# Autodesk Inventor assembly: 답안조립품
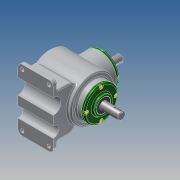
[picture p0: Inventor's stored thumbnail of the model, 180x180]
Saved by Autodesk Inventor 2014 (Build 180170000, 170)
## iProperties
Created: 2018-08
Part Number: 답안조립품
Document SubType Name: Assembly
Designer: kb542
Author: kb542
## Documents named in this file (14)
- C:\Users\kb542\Desktop\480807V1010\답안조립품.iam
- C:\Users\kb542\Desktop\480807V1010\본체.ipt
- C:\Users\kb542\Desktop\480807V1010\메인 축.ipt
- 메인 축.ipt
- C:\Users\kb542\Desktop\480807V1010\키 5x5.ipt
- C:\Users\kb542\Desktop\480807V1010\베어링 6203.ipt
- C:\Users\kb542\Desktop\480807V1010\커버.ipt
- C:\Users\kb542\Desktop\480807V1010\오일실 17 32 8.ipt
- C:\Users\kb542\Desktop\480807V1010\볼트 M4.ipt
- C:\Users\kb542\Desktop\480807V1010\서브 축.ipt
- 서브 축.ipt
- C:\Users\kb542\Desktop\480807V1010\키 4x4.ipt
- C:\Users\kb542\Desktop\480807V1010\메인 베벨기어.ipt
- C:\Users\kb542\Desktop\480807V1010\서브 베벨기어.ipt
